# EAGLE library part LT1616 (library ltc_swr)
LT1616 - 600mA, 1.4MHz Step-Down Switching Regulator in SOT-23 Wide Input Range: 3.6V to 25V 5V at 400mA from7V to 25V Input 3.3V at 400mA from 4.7V to 25V Input Fixed Frequency 1.4MHz Operation Uses Tiny Capacitors and Inductors Internally Compensated Low Shutdown Current: <1&micro;A Low VCESAT Switch: 220mV at 300mA Tiny 6-Lead SOT-23 Package
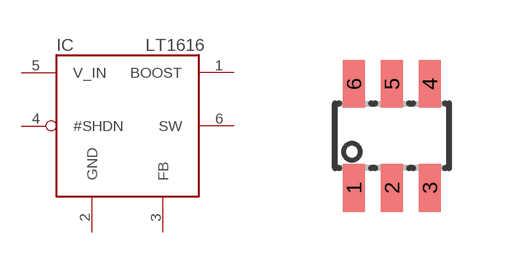
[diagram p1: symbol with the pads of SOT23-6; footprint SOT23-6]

Designator prefix IC

## LT1616  [SOT23-6]
1  BOOST  pas
2  GND  pwr
3  FB  pas
4  #SHDN  pas
5  V_IN  pas
6  SW  pas

## Footprint SOT23-6 (pad centres in mm)
smd 0.55 x 1.2: 1 -0.95,-1.3; 2 0,-1.3; 3 0.95,-1.3; 4 0.95,1.3; 5 0,1.3; 6 -0.95,1.3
